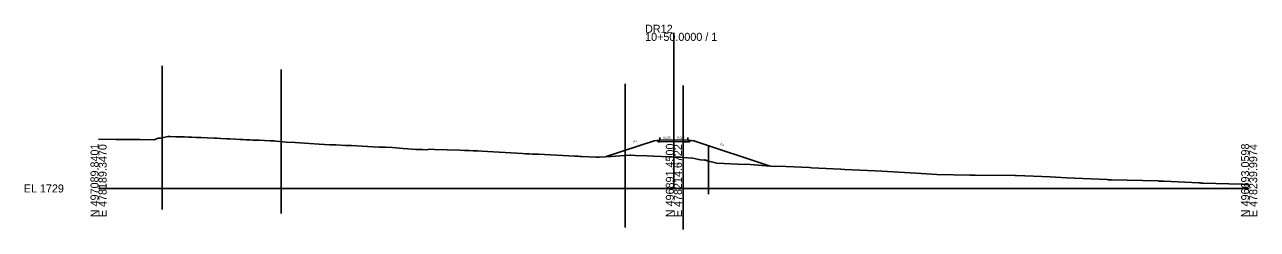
# Model space of a CAD drawing. Extents: x -26 to 403, y -10 to 3574.
# Drawn here: x -25.7 to 402.8, y 985.8 to 1057 of the extents above; entities that cross this region are included whole.
import ezdxf

# ---------------------------------------------------------------- set-up
doc = ezdxf.new("R2010")
doc.units = 0
for name, color, linetype in [('Exist Cross Section Cell', 7, 'Continuous'), ('Exist XS Center Line Elevation Label', 7, 'Continuous'), ('Exist XS Ground Line', 7, 'Continuous'), ('Prop XS Earthwork Shape', 7, 'Continuous'), ('Prop XS EOT Tick Mark', 7, 'Continuous'), ('Prop XS Finish Grade', 7, 'Continuous'), ('Prop XS Finish Grade Earthwork', 7, 'Continuous'), ('Prop XS Finish Grade Pavement', 7, 'Continuous'), ('Prop XS Pvmt Edge Slope', 7, 'Continuous'), ('Prop XS SE Text', 7, 'Continuous'), ('Prop XS Shoulder Borrow Shape', 7, 'Continuous'), ('Prop XS Side Slope Text', 7, 'Continuous'), ('Prop XS Subgrade Earthwork', 7, 'Continuous'), ('Scratch_Level_0', 7, 'Continuous'), ('Scratch_Level_1', 7, 'Continuous'), ('Scratch_Level_4', 7, 'Continuous')]:
    doc.layers.add(name, color=color, linetype=linetype)

msp = doc.modelspace()

# ---------------------------------------------------------------- linework, layer by layer
at = {"layer": 'Exist Cross Section Cell'}
for p, q in [((200, 1000), (200, 1054.12)), ((0, 1000), (200, 1000)), ((200, 1000), (400, 1000))]:
    msp.add_line(p, q, dxfattribs=at)
at = {"layer": 'Exist XS Ground Line'}
msp.add_lwpolyline([(0, 1017.19), (5.99, 1017.01), (12.78, 1017.06), (14.34, 1016.96), (19.24, 1016.86), (19.71, 1016.97), (20.76, 1017.47), (21.46, 1017.53), (22.13, 1017.64), (24.03, 1018.04), (24.92, 1018.01), (26.76, 1017.98), (27.43, 1017.95), (28.97, 1017.92), (29.93, 1017.89), (31.21, 1017.85), (32.44, 1017.81), (34.08, 1017.74), (34.96, 1017.72), (35.65, 1017.69), (37.72, 1017.6), (40.2, 1017.49), (41.28, 1017.45), (42.54, 1017.4), (44.62, 1017.3), (45.05, 1017.27), (45.64, 1017.23), (47.59, 1017.12), (49.09, 1017.05), (50.12, 1017), (51.34, 1016.95), (52.64, 1016.88), (53.63, 1016.84), (55.13, 1016.77), (55.78, 1016.75), (57.65, 1016.66), (59.71, 1016.59), (60.05, 1016.58), (61.12, 1016.53), (61.67, 1016.49), (65.34, 1016.14), (68.37, 1015.95), (73.32, 1015.59), (76.72, 1015.35), (80.35, 1015.19), (82.5, 1015.11), (85.87, 1014.98), (87.91, 1014.91), (95.35, 1014.47), (97.5, 1014.39), (99.76, 1014.3), (102.13, 1014.21), (105.74, 1013.94), (107.56, 1013.74), (108.99, 1013.68), (110.29, 1013.53), (111.45, 1013.49), (112.66, 1013.52), (114.04, 1013.47), (115.18, 1013.62), (116.82, 1013.55), (125.57, 1013.27), (127.16, 1013.21), (128.72, 1013.15), (130.26, 1013.09), (131.77, 1013.03), (133.26, 1012.97), (147.35, 1012.11), (148.53, 1012.06), (149.69, 1012.01), (150.85, 1011.96), (151.94, 1011.91), (152.92, 1011.86), (165.52, 1011.23), (166.77, 1011.17), (167.28, 1011.15), (168, 1011.11), (173.01, 1010.93), (173.45, 1010.91), (174.03, 1010.91), (176.25, 1011.04), (177.42, 1011.07), (178.15, 1011.05), (181.27, 1011.31), (184.72, 1011.55), (185.07, 1011.54), (186.53, 1011.45), (190.64, 1011.31), (192.9, 1011.25), (198.61, 1010.99), (200, 1010.93), (200.96, 1010.88), (202.32, 1010.84), (202.98, 1010.79), (206.59, 1010.51), (208.67, 1010.02), (209.24, 1009.97), (210.61, 1009.83), (210.86, 1009.89), (211.55, 1009.57), (214.97, 1008.78), (224.52, 1008.36), (225.1, 1008.39), (235.07, 1007.63), (236.09, 1007.7), (247.11, 1007.24), (247.86, 1007.17), (258, 1006.73), (259.34, 1006.6), (269.97, 1006.17), (272.27, 1006.06), (284.15, 1005.27), (291.47, 1004.89), (302.86, 1004.67), (304.75, 1004.59), (318.48, 1004.47), (319.16, 1004.44), (330.87, 1004), (336.55, 1003.73), (350.61, 1003.06), (350.93, 1003.04), (351.24, 1003.03), (351.55, 1003.01), (352.14, 1002.99), (368.34, 1002.59), (368.76, 1002.57), (369.18, 1002.56), (369.61, 1002.54), (370.04, 1002.52), (370.47, 1002.5), (382.55, 1001.91), (382.92, 1001.9), (383.28, 1001.88), (383.64, 1001.87), (383.99, 1001.85), (397.34, 1001.46), (397.81, 1001.44), (398.28, 1001.42), (398.75, 1001.4), (399.21, 1001.38), (400, 1001.36)], dxfattribs=at)
at = {"layer": 'Prop XS Earthwork Shape'}
msp.add_lwpolyline([(204.89, 1016.22), (205.44, 1016.21), (205.91, 1016.68), (206.89, 1016.6), (233.43, 1007.75), (225.1, 1008.39), (224.52, 1008.36), (214.97, 1008.78), (211.55, 1009.57), (210.86, 1009.89), (210.61, 1009.83), (209.24, 1009.97), (208.67, 1010.02), (206.59, 1010.51), (202.98, 1010.79), (202.32, 1010.84), (200.96, 1010.88), (200, 1010.93), (198.61, 1010.99), (192.9, 1011.25), (190.64, 1011.31), (186.53, 1011.45), (185.07, 1011.54), (184.72, 1011.55), (181.27, 1011.31), (178.15, 1011.05), (177.42, 1011.07), (176.45, 1011.05), (193.11, 1016.6), (194.09, 1016.68), (194.56, 1016.21), (195.11, 1016.22), (200, 1016.32), (203.27, 1016.25)], close=True, dxfattribs=at)
at = {"layer": 'Prop XS EOT Tick Mark'}
for p, q in [((195.11, 1016.76), (195.11, 1017.76)), ((204.89, 1016.76), (204.89, 1017.76))]:
    msp.add_line(p, q, dxfattribs=at)
at = {"layer": 'Prop XS Finish Grade'}
for p, q in [((195.11, 1016.76), (194.09, 1016.68)), ((204.89, 1016.76), (205.91, 1016.68))]:
    msp.add_line(p, q, dxfattribs=at)
at = {"layer": 'Prop XS Finish Grade Earthwork'}
for p, q in [((193.11, 1016.6), (176.45, 1011.05)), ((194.09, 1016.68), (193.11, 1016.6)), ((205.91, 1016.68), (206.89, 1016.6)), ((206.89, 1016.6), (233.43, 1007.75))]:
    msp.add_line(p, q, dxfattribs=at)
at = {"layer": 'Prop XS Finish Grade Pavement'}
for p, q in [((195.11, 1016.76), (200, 1016.86)), ((200, 1016.86), (204.89, 1016.76))]:
    msp.add_line(p, q, dxfattribs=at)
at = {"layer": 'Prop XS Pvmt Edge Slope'}
for p, q in [((195.11, 1016.76), (194.56, 1016.21)), ((204.89, 1016.76), (205.44, 1016.21))]:
    msp.add_line(p, q, dxfattribs=at)
at = {"layer": 'Prop XS Shoulder Borrow Shape'}
for points in [[(195.11, 1016.76), (194.09, 1016.68), (194.56, 1016.21)], [(204.89, 1016.76), (205.91, 1016.68), (205.44, 1016.21)]]:
    msp.add_lwpolyline(points, close=True, dxfattribs=at)
at = {"layer": 'Prop XS Subgrade Earthwork'}
for p, q in [((194.56, 1016.21), (194.09, 1016.68)), ((195.11, 1016.22), (194.56, 1016.21)), ((200, 1016.32), (195.11, 1016.22)), ((203.27, 1016.25), (200, 1016.32)), ((203.27, 1016.25), (204.89, 1016.22)), ((204.89, 1016.22), (205.44, 1016.21)), ((205.44, 1016.21), (205.91, 1016.68))]:
    msp.add_line(p, q, dxfattribs=at)
at = {"layer": 'Scratch_Level_0'}
msp.add_line((212, 998.06), (212, 1014.9), dxfattribs=at)
at = {"layer": 'Scratch_Level_1'}
for p, q in [((22.13, 1042.64), (22.13, 992.64)), ((63.46, 1041.32), (63.46, 991.32)), ((183.04, 1036.43), (183.04, 986.43)), ((203.27, 1035.77), (203.27, 985.77))]:
    msp.add_line(p, q, dxfattribs=at)
at = {"layer": 'Scratch_Level_4'}
msp.add_line((206.89, 1016.6), (233.43, 1007.75), dxfattribs=at)

# ---------------------------------------------------------------- texts
at = {"layer": 'Exist Cross Section Cell'}
for s, p in [('10+50.0000 / 1', (190, 1051.32)), ('DR12', (190, 1054.12)), ('EL 1729', (-26, 998.6))]:
    msp.add_text(s, height=2.8, dxfattribs=at).set_placement(p)
for s, p in [('N 497089.8401', (0, 990)), ('E 478189.3470', (2.8, 990)), ('N 496891.4500', (200, 990)), ('E 478214.6722', (202.8, 990)), ('N 496693.0598', (400, 990)), ('E 478239.9974', (402.8, 990))]:
    msp.add_text(s, height=2.8, rotation=90, dxfattribs=at).set_placement(p)
at = {"layer": 'Exist XS Center Line Elevation Label'}
msp.add_text('1739.93', height=0.75, dxfattribs=at).set_placement((198.23, 1008.18))
at = {"layer": 'Prop XS SE Text'}
for rotation, p in [(1.1458, (196.27, 1017.28)), (358.8542, (201.15, 1017.33))]:
    msp.add_text('0.020', height=0.75, rotation=rotation, dxfattribs=at).set_placement(p)
at = {"layer": 'Prop XS Side Slope Text'}
for rotation, p in [(18.4349, (185.97, 1015.8)), (341.5651, (215.96, 1015.16))]:
    msp.add_text('3:1', height=0.75, rotation=rotation, dxfattribs=at).set_placement(p)

doc.saveas('drawing.dxf')
